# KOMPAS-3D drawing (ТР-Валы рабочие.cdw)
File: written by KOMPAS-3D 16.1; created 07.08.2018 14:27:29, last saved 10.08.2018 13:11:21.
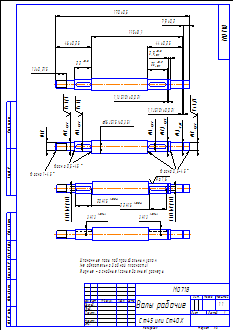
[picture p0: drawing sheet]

Sheet 1: A3, portrait

Title block, sheet 1: name: Валы рабочие; designation: М0718; material: Ст45 или Ст40Х; scale: 1:1; sheets: 1; sheet format: A3; stored path: C:\Users\User\Desktop\Станки\Малый 0718\ТР-Валы рабочие.cdw

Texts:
  User
  JS10( 0,02)
  JS10
  JS15( 0,35)
  JS15
  Фаска 0,5 45
  Фаска 1 45
  JS9( 0,015)
  JS9
  Шпоночные пазы под произвольным углом
  (не обязательно в одной плоскости)
  Жирные - основные (самые важные) размеры
  Ra 1,6
  Ra 1,25
Dimensions and other numbers on the sheet: 44±0,25; 25; 1,1; 2,9; 115; 22; 13±0,215; 170±0,5; 7,9±0,2; 10; 16; 12,4; 9,6; 46±0,25; 20; 5; 3; 1:1; 1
